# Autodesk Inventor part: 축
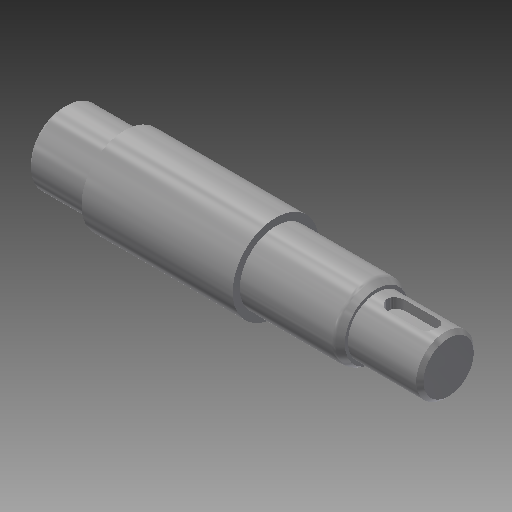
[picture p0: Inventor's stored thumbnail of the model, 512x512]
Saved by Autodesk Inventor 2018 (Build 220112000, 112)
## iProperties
Created: 2016-06
Part Number: 축
Material: 강철, 연강
Document SubType Name: Modeling
Designer: mduedu
Density: 7.86 g/cm^3
Appearance: 강철
Author: mduedu
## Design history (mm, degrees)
sketch "스케치1"
  geometry: L1 (-53.5, 0)-(53.5, 0); L2 (-53.5, 0)-(-53.5, 10); L3 (-53.5, 10)-(-36.5, 10); L4 (-36.5, 10)-(-36.5, 12); L5 (-36.5, 12)-(5.5, 12); L6 (5.5, 12)-(5.5, 10); L7 (5.5, 10)-(33.5, 10); L8 (33.5, 10)-(33.5, 8); L9 (33.5, 8)-(53.5, 8); L10 (53.5, 8)-(53.5, 0); 2 further points
  constraints: 20 end point, 5 parallel, 2 perpendicular, 1 coincident, 1 collinear, 1 horizontal, 1 midpoint, 1 vertical
  dimensions: "d0" = 107 distance of L1.start L1.end; "d2" = 16 diameter of L9 L1; "d3" = 20 diameter of L7 L1; "d4" = 24 diameter of L5 L1; "d5" = 20 diameter of L3 L1; "d6" = 17 distance of L2.end L3.end; "d7" = 20 distance of L8.end L9.end; "d8" = 48 distance from line of L5.end L10
revolve "회전1" sketch "스케치1" stored, may be unused: angle "d9" = 90 deg
chamfer "모따기1" distance "d10" = 2; stored, may be unused: second distance "d11" = 2, angle "d12" = 30 deg
fillet "모깎기1" dims "d13" = 2
node "작업 평면1"
sketch "스케치2"
  geometry: L1 (-4.5, 2.5)-(4.5, 2.5); L2 (4.5, -2.5)-(-4.5, -2.5); L3 (-4.5, 0)-(4.5, 0); L4 (-10, 8.845)-(-10, -8.845) reference; A1 r 2.5 centre (-4.5, 0) between (-4.5, 2.5) and (-4.5, -2.5); A2 r 2.5 centre (4.5, 0) between (4.5, -2.5) and (4.5, 2.5); 1 further point
  constraints: 6 end point, 4 point on circle, 3 tangent, 2 centre point, 2 parallel, 1 horizontal, 1 horizontal alignment
  dimensions: "d14" = 3 distance edge to line of A1 L4; "d15" = 5 distance between parallel lines of L2 L1; "d16" = 14 dimension on A2 A1
extrude "돌출1" cut sketch "스케치2" distance "d17" = 3; taper "d18" = 0 deg
chamfer "모따기2" distance "d19" = 1; stored, may be unused: second distance "d20" = 2, angle "d21" = 30 deg
sketch "스케치3"
  geometry: L1 (-33.5, -8)-(-52.5, -8) reference; L2 (-53.5, -7)-(-53.5, 7) reference; L3 (-36, -8)-(-37.5, -6.5); L4 (-37.5, -6.5)-(-37.5, -8); L5 (-36, -8)-(-37.5, -8); 1 further point
  constraints: 6 end point, 2 point on line, 1 collinear, 1 vertical
  dimensions: "d22" = 45 deg angle of L4 L3; "d23" = 16 distance between parallel lines of L2 L4; "d24" = 3 diameter of L3.start L4
revolve "회전2" stored, may be unused: angle "d25" = 90 deg
node "작업점1"
sketch "스케치4"
  geometry: 1 further point
hole "구멍1" sketch "스케치4" at (0, 0) diameter "d26" = 3.242; stored, may be unused: countersink angle "d30" = 90 deg, drill point angle "d32" = 120 deg; dims "d27" = 8, "d28" = 4, "d29" = 2, "d31" = 11
chamfer "모따기3" distance "d33" = 2; stored, may be unused: second distance "d34" = 2, angle "d35" = 30 deg
node "솔리드1"
